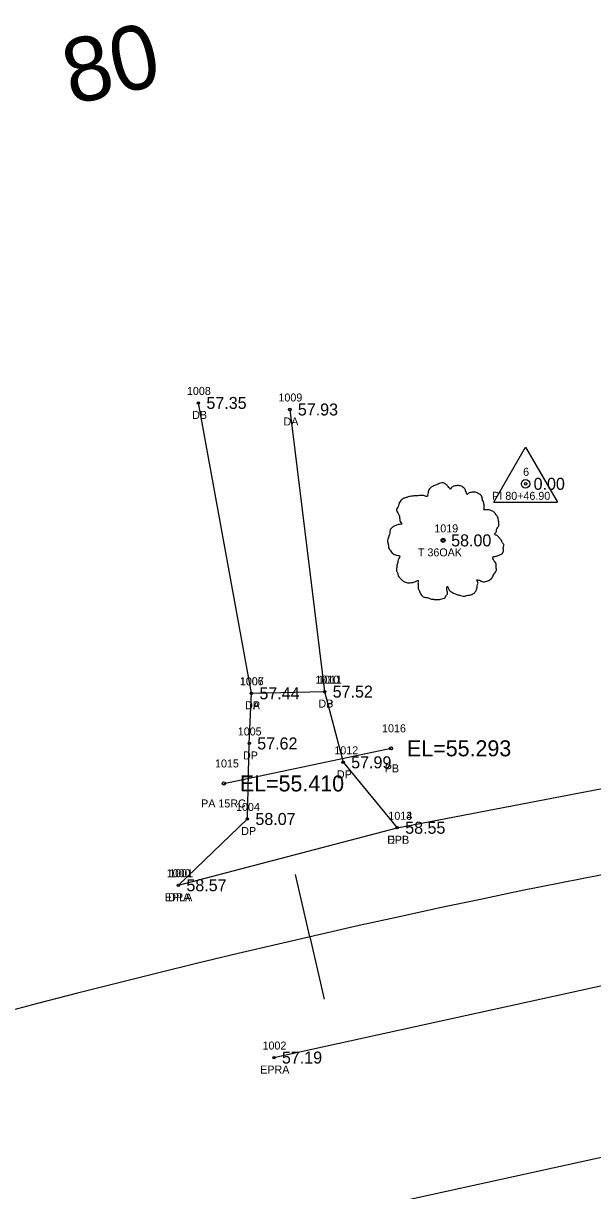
# Model space of a CAD drawing. Extents: x 2420113 to 2422887, y 845323 to 846653.
# Drawn here: x 2420357 to 2420428.1, y 845663.8 to 845809.7 of the extents above; entities that cross this region are included whole.
import ezdxf

# ---------------------------------------------------------------- set-up
doc = ezdxf.new("R2010")
doc.units = 0
for name, color, linetype in [('RD_EX_DR_Pipe', 7, 'Continuous'), ('RD_EX_DR_Pipe_txCode', 7, 'Continuous'), ('RD_EX_Driveway', 7, 'Continuous'), ('RD_EX_Driveway_txCode', 7, 'Continuous'), ('RD_EX_Road', 7, 'Continuous'), ('RD_EX_Road_txCode', 7, 'Continuous'), ('RD_EX_TX_Driveway_ELEV', 7, 'Continuous'), ('RD_EX_TX_Road_ELEV', 7, 'Continuous'), ('RD_EX_TX_VEG_ELEV', 7, 'Continuous'), ('RD_EX_VEG', 7, 'Continuous'), ('RD_EX_VEG_txCode', 7, 'Continuous'), ('RD_HC_Cl', 7, 'Continuous'), ('RD_HC_Data', 7, 'Continuous'), ('RD_HC_Data_Tic', 7, 'Continuous'), ('RD_HC_Survey_ELEV', 7, 'Continuous'), ('RD_HC_TX_Sta50', 7, 'Continuous'), ('RD_HC_txCode', 7, 'Continuous'), ('RD_SMD_Locator', 7, 'Continuous'), ('RD_TX_Pipe_ElevEX', 7, 'Continuous')]:
    doc.layers.add(name, color=color, linetype=linetype)

msp = doc.modelspace()

# ---------------------------------------------------------------- linework, layer by layer
at = {"layer": 'RD_EX_DR_Pipe'}
msp.add_line((2420382.03, 845714.65), (2420402.91, 845719.04), dxfattribs=at)
at = {"layer": 'RD_EX_Driveway'}
for p, q in [((2420385.47, 845725.92), (2420378.85, 845762.21)), ((2420390.27, 845761.39), (2420394.62, 845726.13))]:
    msp.add_line(p, q, dxfattribs=at)
msp.add_lwpolyline([(2420376.35, 845701.93), (2420384.97, 845710.21), (2420385.2, 845719.65), (2420385.47, 845725.92), (2420394.62, 845726.13), (2420396.93, 845717.29), (2420403.68, 845709.11)], dxfattribs=at)
at = {"layer": 'RD_EX_Road'}
for points in [[(2420388.28, 845680.39), (2420441.29, 845692.04), (2420492.62, 845700.7), (2420553.92, 845707.41), (2420607.69, 845710.85), (2420682.38, 845711.26), (2420749.44, 845707.27), (2420795.12, 845703.44), (2420900.28, 845693.42), (2421017.17, 845682.19), (2421113.9, 845672.97), (2421174.87, 845668.16), (2421234.59, 845666.13), (2421293, 845667.25), (2421351.24, 845671.5), (2421419.82, 845681.17), (2421463.19, 845688.63), (2421558.82, 845713.18), (2421614.57, 845730.45), (2421670.73, 845751.42), (2421735.61, 845780.5), (2421750.75, 845787.87), (2421744.67, 845798.22), (2421739.21, 845808.11)], [(2420376.35, 845701.93), (2420403.68, 845709.11), (2420436.45, 845715.41), (2420465.85, 845720.8), (2420487.58, 845724.76), (2420551.29, 845731.53), (2420607.05, 845734.89), (2420658.72, 845735.59), (2420682.86, 845735.47), (2420736.67, 845732.56), (2420795.4, 845727.65), (2420889.7, 845718.98), (2420911.08, 845716.87), (2420953.91, 845713.71), (2420998.34, 845708.25), (2421018.47, 845706.55), (2421116.02, 845696.98), (2421176.98, 845692), (2421235.85, 845690.14), (2421292.32, 845691.44), (2421350.22, 845695.49), (2421412.35, 845704.28)]]:
    msp.add_lwpolyline(points, dxfattribs=at)
at = {"layer": 'RD_EX_VEG'}
msp.add_lwpolyline([(2420391.44, 845659.63), (2420497.12, 845682.87), (2420554.96, 845697.51), (2420665.26, 845702.88), (2420735.64, 845697.65), (2420790.66, 845674.79), (2421018.22, 845655.05), (2421176.12, 845636.22), (2421296.76, 845636.57), (2421411.61, 845653.11), (2421415.24, 845569.55)], dxfattribs=at)
for centre, radius in [((2420409.42, 845745.03), 0.25), ((2420409.41, 845745.01), 0.0001)]:
    msp.add_circle(centre, radius, dxfattribs=at)
for points in [[(2420409.56, 845752.2), (2420409.26, 845752.22), (2420408.93, 845752.12), (2420408.68, 845752.02), (2420408.46, 845751.95), (2420408.23, 845751.85), (2420407.93, 845751.67), (2420407.71, 845751.47), (2420407.58, 845751.22), (2420407.53, 845751), (2420407.48, 845750.72), (2420407.48, 845750.55), (2420407.36, 845750.52), (2420407.21, 845750.55), (2420406.96, 845750.62), (2420406.71, 845750.62), (2420406.46, 845750.62), (2420406.11, 845750.6), (2420405.76, 845750.6), (2420405.48, 845750.55), (2420405.16, 845750.5), (2420404.78, 845750.37), (2420404.43, 845750.25), (2420404.13, 845750), (2420403.88, 845749.52), (2420403.76, 845749.17), (2420403.61, 845748.92), (2420403.76, 845748.47), (2420403.93, 845748.12), (2420403.96, 845747.92), (2420404.03, 845747.5), (2420404.13, 845747.27), (2420404.26, 845747.07), (2420404.18, 845747.05), (2420403.81, 845747), (2420403.51, 845746.9), (2420403.08, 845746.67), (2420402.86, 845746.45), (2420402.76, 845746.12), (2420402.73, 845745.77), (2420402.63, 845745.57), (2420402.56, 845745.3), (2420402.53, 845745.22), (2420402.48, 845744.9), (2420402.58, 845744.45), (2420402.61, 845744.1), (2420402.73, 845743.88), (2420402.88, 845743.7), (2420403.06, 845743.45), (2420403.46, 845743.23), (2420403.78, 845743.13), (2420403.98, 845743.1), (2420403.81, 845742.6), (2420403.76, 845742.25), (2420403.63, 845741.85), (2420403.63, 845741.78), (2420403.58, 845741.3), (2420403.73, 845740.98), (2420403.81, 845740.6), (2420403.98, 845740.38), (2420404.26, 845740.08), (2420404.58, 845739.85), (2420405.08, 845739.73), (2420405.48, 845739.75), (2420406.06, 845739.93), (2420406.31, 845740), (2420406.28, 845739.83), (2420406.31, 845739.45), (2420406.31, 845739.03), (2420406.46, 845738.7), (2420406.56, 845738.43), (2420406.71, 845738.18), (2420407.03, 845737.95), (2420407.43, 845737.88), (2420407.86, 845737.73), (2420408.31, 845737.65), (2420408.81, 845737.63), (2420409.41, 845737.78), (2420409.68, 845737.9), (2420409.78, 845738.08), (2420409.98, 845738.45), (2420409.93, 845738.68), (2420409.96, 845739.28), (2420410.06, 845739.1), (2420410.23, 845738.75), (2420410.73, 845738.45), (2420411.13, 845738.28), (2420411.6, 845738.13), (2420411.9, 845738.05), (2420412.38, 845738.13), (2420412.75, 845738.2), (2420413.13, 845738.33), (2420413.43, 845738.6), (2420413.6, 845738.88), (2420413.65, 845739.15), (2420413.73, 845739.53), (2420413.78, 845739.7)], [(2420413.78, 845739.7), (2420413.7, 845739.88), (2420413.65, 845740.13), (2420413.73, 845740.1), (2420413.9, 845740.05), (2420414.18, 845739.93), (2420414.4, 845739.85), (2420414.73, 845739.88), (2420415, 845739.98), (2420415.45, 845740.25), (2420415.73, 845740.73), (2420416, 845741.13), (2420416.08, 845741.45), (2420416.03, 845741.68), (2420416, 845742.18), (2420415.8, 845742.43), (2420415.75, 845742.55), (2420415.65, 845742.95), (2420415.73, 845743), (2420416, 845743.05), (2420416.38, 845743.18), (2420416.65, 845743.3), (2420416.88, 845743.48), (2420416.95, 845743.7), (2420416.93, 845744.1), (2420416.98, 845744.5), (2420416.9, 845744.65), (2420416.8, 845744.8), (2420416.73, 845745), (2420416.58, 845745.15), (2420416.48, 845745.3), (2420416.38, 845745.4), (2420416.25, 845745.55), (2420416.08, 845745.67), (2420415.93, 845745.72), (2420415.88, 845745.87), (2420416.03, 845746.07), (2420416.08, 845746.17), (2420416.1, 845746.4), (2420416.33, 845746.75), (2420416.38, 845747.15), (2420416.33, 845747.57), (2420416.28, 845747.85), (2420416.13, 845748.12), (2420415.93, 845748.37), (2420415.8, 845748.55), (2420415.63, 845748.67), (2420415.3, 845748.8), (2420415.05, 845748.85), (2420414.7, 845748.85), (2420414.5, 845748.9), (2420414.53, 845748.95), (2420414.53, 845749.1), (2420414.53, 845749.37), (2420414.45, 845749.82), (2420414.3, 845750.32), (2420414.3, 845750.35), (2420414.2, 845750.6), (2420413.98, 845750.8), (2420413.8, 845750.9), (2420413.6, 845751.02), (2420413.35, 845751.05), (2420413.05, 845751.05), (2420412.78, 845751), (2420412.58, 845750.9), (2420412.4, 845750.77), (2420412.33, 845750.92), (2420412.23, 845751.22), (2420412.18, 845751.37), (2420412.03, 845751.55), (2420411.8, 845751.75), (2420411.35, 845751.87), (2420410.73, 845751.8), (2420410.43, 845751.6), (2420410.28, 845751.42), (2420410.23, 845751.55), (2420410.03, 845751.75), (2420409.93, 845751.92), (2420409.76, 845752.05), (2420409.61, 845752.15), (2420409.51, 845752.2)]]:
    msp.add_spline(points, degree=3, dxfattribs=at)
at = {"layer": 'RD_HC_Cl'}
msp.add_arc((2420649.07, 844578.36), 1146.15, 84.46476, 117.6481, dxfattribs=at)
at = {"layer": 'RD_HC_Data'}
for p, q in [((2420415.75, 845749.81), (2420419.72, 845756.69)), ((2420419.72, 845756.69), (2420423.69, 845749.81)), ((2420415.75, 845749.81), (2420423.69, 845749.81))]:
    msp.add_line(p, q, dxfattribs=at)
msp.add_circle((2420419.72, 845752.1), 0.529, dxfattribs=at)
at = {"layer": 'RD_HC_Data_Tic'}
for q in [(2420390.99, 845703.28), (2420394.57, 845687.68)]:
    msp.add_line((2420392.78, 845695.48), q, dxfattribs=at)
at = {"layer": 'RD_SMD_Locator'}
for centre, radius in [((2420378.85, 845762.21), 0.15), ((2420390.27, 845761.39), 0.15), ((2420419.72, 845752.1), 0.15), ((2420409.42, 845745.03), 0.15), ((2420385.47, 845725.92), 0.15), ((2420385.47, 845725.92), 0.15), ((2420394.62, 845726.13), 0.15), ((2420394.62, 845726.13), 0.15), ((2420385.2, 845719.65), 0.15), ((2420402.91, 845719.04), 0.2), ((2420396.93, 845717.29), 0.15), ((2420382.03, 845714.65), 0.2), ((2420384.97, 845710.21), 0.15), ((2420403.68, 845709.11), 0.15), ((2420403.68, 845709.11), 0.15), ((2420376.35, 845701.93), 0.15), ((2420376.35, 845701.93), 0.15), ((2420388.28, 845680.39), 0.15)]:
    msp.add_circle(centre, radius, dxfattribs=at)

# ---------------------------------------------------------------- texts
at = {"layer": 'RD_EX_DR_Pipe_txCode'}
for s, p in [('1016', (2420401.79, 845721.04)), ('1015', (2420380.93, 845716.65)), ('PB', (2420402.13, 845716.04)), ('PA 15RC', (2420379.19, 845711.65))]:
    msp.add_text(s, height=1, dxfattribs=at).set_placement(p)
at = {"layer": 'RD_EX_Driveway_txCode'}
for s, p in [('1008', (2420377.42, 845763.21)), ('1009', (2420388.85, 845762.39)), ('DB', (2420378.07, 845760.21)), ('DA', (2420389.48, 845759.39)), ('1006', (2420384.02, 845726.92)), ('1007', (2420384.04, 845726.92)), ('1010', (2420393.47, 845727.13)), ('1011', (2420393.8, 845727.13)), ('DA', (2420384.67, 845723.92)), ('DP', (2420384.69, 845723.92)), ('DB', (2420393.84, 845724.13)), ('DP', (2420393.84, 845724.13)), ('1005', (2420383.77, 845720.65)), ('DP', (2420384.42, 845717.65)), ('1012', (2420395.83, 845718.29)), ('DP', (2420396.15, 845715.29)), ('1004', (2420383.55, 845711.21)), ('1013', (2420402.58, 845710.11)), ('DP', (2420384.2, 845708.21)), ('DPB', (2420402.43, 845707.11)), ('1001', (2420375.21, 845702.93)), ('DPA', (2420375.08, 845699.93))]:
    msp.add_text(s, height=1, dxfattribs=at).set_placement(p)
at = {"layer": 'RD_EX_Road_txCode'}
for s, p in [('1014', (2420402.58, 845710.11)), ('EPL', (2420402.48, 845707.11)), ('1000', (2420374.89, 845702.93)), ('EPLA', (2420374.66, 845699.93)), ('1002', (2420386.86, 845681.39)), ('EPRA', (2420386.57, 845678.39))]:
    msp.add_text(s, height=1, dxfattribs=at).set_placement(p)
at = {"layer": 'RD_EX_TX_Driveway_ELEV'}
for s, p in [('57.35', (2420379.85, 845761.46)), ('57.93', (2420391.27, 845760.64)), ('57.44', (2420386.47, 845725.17)), ('57.44', (2420386.47, 845725.17)), ('57.52', (2420395.62, 845725.38)), ('57.52', (2420395.62, 845725.38)), ('57.62', (2420386.2, 845718.9)), ('57.99', (2420397.93, 845716.54)), ('58.07', (2420385.97, 845709.46)), ('58.55', (2420404.68, 845708.36)), ('58.57', (2420377.35, 845701.18))]:
    msp.add_text(s, height=1.5, dxfattribs=at).set_placement(p)
at = {"layer": 'RD_EX_TX_Road_ELEV'}
for s, p in [('58.55', (2420404.68, 845708.36)), ('58.57', (2420377.35, 845701.18)), ('57.19', (2420389.28, 845679.64))]:
    msp.add_text(s, height=1.5, dxfattribs=at).set_placement(p)
at = {"layer": 'RD_EX_TX_VEG_ELEV'}
msp.add_text('58.00', height=1.5, dxfattribs=at).set_placement((2420410.42, 845744.28))
at = {"layer": 'RD_EX_VEG_txCode'}
for s, p in [('1019', (2420408.32, 845746.03)), ('T 36OAK', (2420406.27, 845743.03))]:
    msp.add_text(s, height=1, dxfattribs=at).set_placement(p)
at = {"layer": 'RD_HC_Survey_ELEV'}
msp.add_text('0.00', height=1.5, dxfattribs=at).set_placement((2420420.72, 845751.35))
at = {"layer": 'RD_HC_TX_Sta50'}
msp.add_text('80', height=8, rotation=12.9211, dxfattribs=at).set_placement((2420362.98, 845799.45))
at = {"layer": 'RD_HC_txCode'}
for s, p in [('6', (2420419.41, 845753.1)), ('PI 80+46.90', (2420415.55, 845750.1))]:
    msp.add_text(s, height=1, dxfattribs=at).set_placement(p)
at = {"layer": 'RD_TX_Pipe_ElevEX'}
for s, p in [('EL=55.293', (2420404.91, 845718.04)), ('EL=55.410', (2420384.03, 845713.65))]:
    msp.add_text(s, height=2, dxfattribs=at).set_placement(p)

doc.saveas('drawing.dxf')
